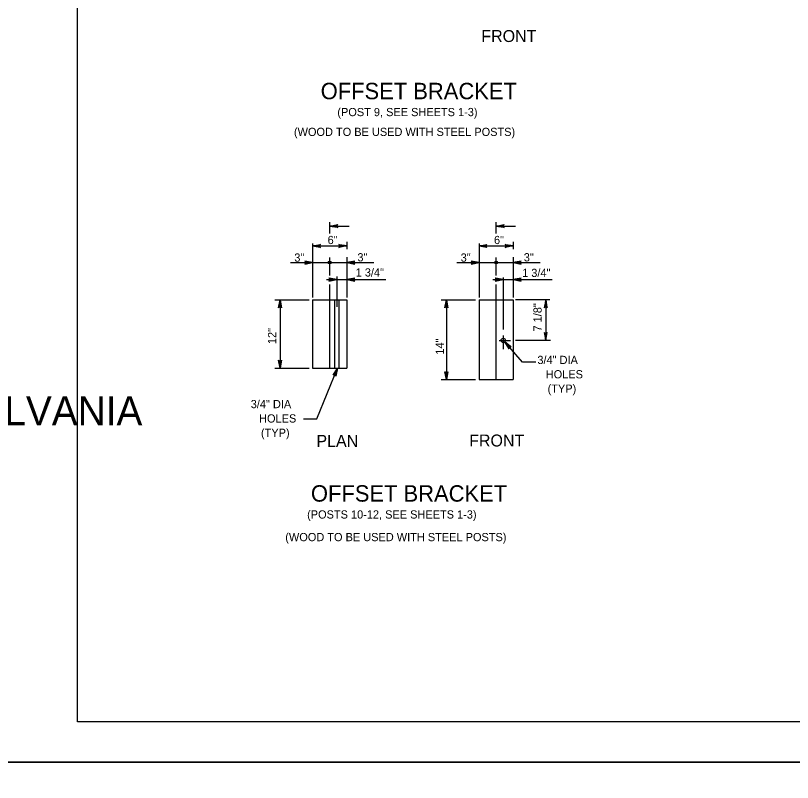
# Model space of a CAD drawing. Extents: x 632007860 to 635435983, y 295418622 to 297794622.
# Drawn here: x 632865880 to 633154598, y 297193122 to 297477992 of the extents above; entities that cross this region are included whole.
import ezdxf

# ---------------------------------------------------------------- set-up
doc = ezdxf.new("R2010")
doc.units = 0
for name, color, linetype in [('1', 7, 'Continuous'), ('8', 7, 'Continuous'), ('PLT-BNDY', 7, 'Continuous'), ('S-DETL-DIMS', 7, 'Continuous'), ('S-DETL-T120', 7, 'Continuous'), ('S-DETL-T175', 7, 'Continuous'), ('S-DETL-T240', 7, 'Continuous'), ('S-MISC-CNTR-WT01', 7, 'Continuous'), ('S-STEL', 7, 'Continuous')]:
    doc.layers.add(name, color=color, linetype=linetype)

msp = doc.modelspace()

# ---------------------------------------------------------------- linework, layer by layer
at = {"layer": '1'}
for p, q in [((632888860, 297215622), (632888860, 297779622)), ((633674860, 297215622), (632888860, 297215622))]:
    msp.add_line(p, q, dxfattribs=at)
at = {"layer": '8'}
for p, q in [((633044469, 297397026), (633044469, 297401243)), ((632982643, 297381483), (632982643, 297388087)), ((633044469, 297381483), (633044469, 297388087)), ((632985298, 297381047), (632985298, 297369752)), ((632982643, 297346747), (632982643, 297378051)), ((633044469, 297343001), (633044469, 297378051)), ((633045557, 297357298), (633049822, 297357298)), ((633047123, 297359084), (633047123, 297354089))]:
    msp.add_line(p, q, dxfattribs=at)
at = {"layer": 'PLT-BNDY'}
for points in [[(632848860, 297794622), (633689860, 297794622), (633689860, 297200622), (632848860, 297200622)], [(632848860, 297200622), (633689860, 297200622), (633689860, 296606622), (632848860, 296606622)]]:
    msp.add_lwpolyline(points, close=True, dxfattribs=at)
at = {"layer": 'S-DETL-DIMS'}
for p, q in [((632982643, 297399763), (632989870, 297399763)), ((633044469, 297399763), (633051696, 297399763)), ((632976285, 297393351), (632976285, 297373261)), ((632976285, 297392393), (632989001, 297392393)), ((632989001, 297393994), (632989001, 297391165)), ((633038111, 297393351), (633038111, 297373261)), ((633038111, 297392393), (633050827, 297392393)), ((633050827, 297393994), (633050827, 297391165)), ((632968104, 297386253), (632982643, 297386253)), ((632982643, 297386253), (632999058, 297386253)), ((632989001, 297388272), (632989001, 297373261)), ((633029930, 297386253), (633044469, 297386253)), ((633044469, 297386253), (633060884, 297386253)), ((633050827, 297388272), (633050827, 297373261)), ((632981467, 297379903), (633003476, 297379903)), ((633043293, 297379903), (633065302, 297379903)), ((633047123, 297380749), (633047123, 297361351)), ((632962247, 297372380), (632974964, 297372380)), ((632964195, 297372380), (632964195, 297346980)), ((633024073, 297372380), (633036790, 297372380)), ((633026021, 297372380), (633026021, 297342747)), ((633064393, 297372380), (633051614, 297372380)), ((633062917, 297372380), (633062917, 297357298)), ((633054311, 297349238), (633047746, 297356807)), ((633064730, 297357298), (633051614, 297357298)), ((633059258, 297349238), (633054311, 297349238)), ((632962247, 297346980), (632974964, 297346980)), ((632977820, 297328187), (632985563, 297346980)), ((633024073, 297342747), (633036790, 297342747)), ((632972874, 297328187), (632977820, 297328187))]:
    msp.add_line(p, q, dxfattribs=at)
for points in [[(632982643, 297399763), (632985603, 297400318), (632985375, 297400160), (632985257, 297399962), (632985223, 297399763), (632985257, 297399565), (632985375, 297399366), (632985603, 297399208), (632982643, 297399763), (632985375, 297399366), (632985257, 297399565), (632982643, 297399763), (632985223, 297399763), (632985257, 297399962), (632982643, 297399763), (632985375, 297400160)], [(633044469, 297399763), (633047428, 297400318), (633047200, 297400160), (633047083, 297399962), (633047049, 297399763), (633047083, 297399565), (633047200, 297399366), (633047428, 297399208), (633044469, 297399763), (633047200, 297399366), (633047083, 297399565), (633044469, 297399763), (633047049, 297399763), (633047083, 297399962), (633044469, 297399763), (633047200, 297400160)], [(632976285, 297392393), (632979245, 297392948), (632979017, 297392790), (632978899, 297392591), (632978865, 297392393), (632978899, 297392194), (632979017, 297391996), (632979245, 297391838), (632976285, 297392393), (632979017, 297391996), (632978899, 297392194), (632976285, 297392393), (632978865, 297392393), (632978899, 297392591), (632976285, 297392393), (632979017, 297392790)], [(632989001, 297392393), (632986042, 297391838), (632986270, 297391996), (632986387, 297392194), (632986422, 297392393), (632986387, 297392591), (632986270, 297392790), (632986042, 297392948), (632989001, 297392393), (632986270, 297392790), (632986387, 297392591), (632989001, 297392393), (632986422, 297392393), (632986387, 297392194), (632989001, 297392393), (632986270, 297391996)], [(633038111, 297392393), (633041070, 297392948), (633040842, 297392790), (633040725, 297392591), (633040691, 297392393), (633040725, 297392194), (633040842, 297391996), (633041070, 297391838), (633038111, 297392393), (633040842, 297391996), (633040725, 297392194), (633038111, 297392393), (633040691, 297392393), (633040725, 297392591), (633038111, 297392393), (633040842, 297392790)], [(633050827, 297392393), (633047868, 297391838), (633048096, 297391996), (633048213, 297392194), (633048247, 297392393), (633048213, 297392591), (633048096, 297392790), (633047868, 297392948), (633050827, 297392393), (633048096, 297392790), (633048213, 297392591), (633050827, 297392393), (633048247, 297392393), (633048213, 297392194), (633050827, 297392393), (633048096, 297391996)], [(632976285, 297386253), (632973326, 297386808), (632973554, 297386650), (632973672, 297386452), (632973706, 297386253), (632973672, 297386055), (632973554, 297385857), (632973326, 297385699), (632976285, 297386253), (632973554, 297385857), (632973672, 297386055), (632976285, 297386253), (632973706, 297386253), (632973672, 297386452), (632976285, 297386253), (632973554, 297386650)], [(632989001, 297386253), (632991961, 297385699), (632991732, 297385857), (632991615, 297386055), (632991581, 297386253), (632991615, 297386452), (632991732, 297386650), (632991961, 297386808), (632989001, 297386253), (632991732, 297386650), (632991615, 297386452), (632989001, 297386253), (632991581, 297386253), (632991615, 297386055), (632989001, 297386253), (632991732, 297385857)], [(633038111, 297386253), (633035152, 297386808), (633035380, 297386650), (633035497, 297386452), (633035531, 297386253), (633035497, 297386055), (633035380, 297385857), (633035152, 297385699), (633038111, 297386253), (633035380, 297385857), (633035497, 297386055), (633038111, 297386253), (633035531, 297386253), (633035497, 297386452), (633038111, 297386253), (633035380, 297386650)], [(633050827, 297386253), (633053786, 297385699), (633053558, 297385857), (633053441, 297386055), (633053407, 297386253), (633053441, 297386452), (633053558, 297386650), (633053786, 297386808), (633050827, 297386253), (633053558, 297386650), (633053441, 297386452), (633050827, 297386253), (633053407, 297386253), (633053441, 297386055), (633050827, 297386253), (633053558, 297385857)], [(632985298, 297379903), (632982339, 297380458), (632982453, 297380379), (632982567, 297380300), (632982625, 297380201), (632982684, 297380102), (632982701, 297380003), (632982718, 297379903), (632982701, 297379804), (632982684, 297379705), (632982625, 297379606), (632982567, 297379507), (632982453, 297379428), (632982339, 297379349), (632985298, 297379903), (632982453, 297379428), (632982567, 297379507), (632985298, 297379903), (632982625, 297379606), (632982684, 297379705), (632985298, 297379903), (632982701, 297379804), (632982718, 297379903), (632985298, 297379903), (632982701, 297380003), (632982684, 297380102), (632985298, 297379903), (632982625, 297380201), (632982567, 297380300), (632985298, 297379903), (632982453, 297380379)], [(632989001, 297379903), (632991961, 297379349), (632991847, 297379428), (632991732, 297379507), (632991674, 297379606), (632991615, 297379705), (632991598, 297379804), (632991581, 297379903), (632991598, 297380003), (632991615, 297380102), (632991674, 297380201), (632991732, 297380300), (632991847, 297380379), (632991961, 297380458), (632989001, 297379903), (632991847, 297380379), (632991732, 297380300), (632989001, 297379903), (632991674, 297380201), (632991615, 297380102), (632989001, 297379903), (632991598, 297380003), (632991581, 297379903), (632989001, 297379903), (632991598, 297379804), (632991615, 297379705), (632989001, 297379903), (632991674, 297379606), (632991732, 297379507), (632989001, 297379903), (632991847, 297379428)], [(633047123, 297379903), (633044163, 297380458), (633044277, 297380379), (633044391, 297380300), (633044450, 297380201), (633044509, 297380102), (633044526, 297380003), (633044543, 297379903), (633044526, 297379804), (633044509, 297379705), (633044450, 297379606), (633044391, 297379507), (633044277, 297379428), (633044163, 297379349), (633047123, 297379903), (633044277, 297379428), (633044391, 297379507), (633047123, 297379903), (633044450, 297379606), (633044509, 297379705), (633047123, 297379903), (633044526, 297379804), (633044543, 297379903), (633047123, 297379903), (633044526, 297380003), (633044509, 297380102), (633047123, 297379903), (633044450, 297380201), (633044391, 297380300), (633047123, 297379903), (633044277, 297380379)], [(633050827, 297379903), (633053786, 297379349), (633053672, 297379428), (633053558, 297379507), (633053499, 297379606), (633053441, 297379705), (633053424, 297379804), (633053407, 297379903), (633053424, 297380003), (633053441, 297380102), (633053499, 297380201), (633053558, 297380300), (633053672, 297380379), (633053786, 297380458), (633050827, 297379903), (633053672, 297380379), (633053558, 297380300), (633050827, 297379903), (633053499, 297380201), (633053441, 297380102), (633050827, 297379903), (633053424, 297380003), (633053407, 297379903), (633050827, 297379903), (633053424, 297379804), (633053441, 297379705), (633050827, 297379903), (633053499, 297379606), (633053558, 297379507), (633050827, 297379903), (633053672, 297379428)], [(632964195, 297372380), (632964750, 297369421), (632964592, 297369649), (632964393, 297369766), (632964195, 297369801), (632963997, 297369766), (632963798, 297369649), (632963640, 297369421), (632964195, 297372380), (632963798, 297369649), (632963997, 297369766), (632964195, 297372380), (632964195, 297369801), (632964393, 297369766), (632964195, 297372380), (632964592, 297369649)], [(633026021, 297372380), (633026576, 297369421), (633026418, 297369649), (633026219, 297369766), (633026021, 297369801), (633025822, 297369766), (633025624, 297369649), (633025466, 297369421), (633026021, 297372380), (633025624, 297369649), (633025822, 297369766), (633026021, 297372380), (633026021, 297369801), (633026219, 297369766), (633026021, 297372380), (633026418, 297369649)], [(633062917, 297372380), (633062362, 297369421), (633062520, 297369649), (633062719, 297369766), (633062917, 297369801), (633063116, 297369766), (633063314, 297369649), (633063472, 297369421), (633062917, 297372380), (633063314, 297369649), (633063116, 297369766), (633062917, 297372380), (633062917, 297369801), (633062719, 297369766), (633062917, 297372380), (633062520, 297369649)], [(633062917, 297357298), (633063472, 297360257), (633063314, 297360029), (633063116, 297359911), (633062917, 297359877), (633062719, 297359911), (633062520, 297360029), (633062362, 297360257), (633062917, 297357298), (633062520, 297360029), (633062719, 297359911), (633062917, 297357298), (633062917, 297359877), (633063116, 297359911), (633062917, 297357298), (633063314, 297360029)], [(633047746, 297356807), (633050104, 297354935), (633049970, 297354969), (633049836, 297355004), (633049722, 297354983), (633049609, 297354962), (633049523, 297354910), (633049437, 297354858), (633049373, 297354780), (633049309, 297354702), (633049273, 297354593), (633049236, 297354483), (633049251, 297354346), (633049266, 297354208), (633047746, 297356807), (633049251, 297354346), (633049236, 297354483), (633047746, 297356807), (633049273, 297354593), (633049309, 297354702), (633047746, 297356807), (633049373, 297354780), (633049437, 297354858), (633047746, 297356807), (633049523, 297354910), (633049609, 297354962), (633047746, 297356807), (633049722, 297354983), (633049836, 297355004), (633047746, 297356807), (633049970, 297354969)], [(632964195, 297346980), (632963640, 297349939), (632963798, 297349711), (632963997, 297349594), (632964195, 297349560), (632964393, 297349594), (632964592, 297349711), (632964750, 297349939), (632964195, 297346980), (632964592, 297349711), (632964393, 297349594), (632964195, 297346980), (632964195, 297349560), (632963997, 297349594), (632964195, 297346980), (632963798, 297349711)], [(632985563, 297346980), (632984949, 297344033), (632984919, 297344168), (632984890, 297344304), (632984820, 297344396), (632984751, 297344488), (632984666, 297344541), (632984581, 297344595), (632984482, 297344617), (632984384, 297344639), (632984270, 297344623), (632984156, 297344606), (632984039, 297344531), (632983923, 297344455), (632985563, 297346980), (632984039, 297344531), (632984156, 297344606), (632985563, 297346980), (632984270, 297344623), (632984384, 297344639), (632985563, 297346980), (632984482, 297344617), (632984581, 297344595), (632985563, 297346980), (632984666, 297344541), (632984751, 297344488), (632985563, 297346980), (632984820, 297344396), (632984890, 297344304), (632985563, 297346980), (632984919, 297344168)], [(633026021, 297342747), (633025466, 297345706), (633025545, 297345592), (633025624, 297345478), (633025723, 297345419), (633025822, 297345360), (633025922, 297345343), (633026021, 297345326), (633026120, 297345343), (633026219, 297345360), (633026318, 297345419), (633026418, 297345478), (633026497, 297345592), (633026576, 297345706), (633026021, 297342747), (633026497, 297345592), (633026418, 297345478), (633026021, 297342747), (633026318, 297345419), (633026219, 297345360), (633026021, 297342747), (633026120, 297345343), (633026021, 297345326), (633026021, 297342747), (633025922, 297345343), (633025822, 297345360), (633026021, 297342747), (633025723, 297345419), (633025624, 297345478), (633026021, 297342747), (633025545, 297345592)]]:
    msp.add_lwpolyline(points, dxfattribs=at)
for centre, radius in [((632982643, 297386253), 529), ((632982643, 297386253), 265), ((633044469, 297386253), 529), ((633044469, 297386253), 265)]:
    msp.add_circle(centre, radius, dxfattribs=at)
at = {"layer": 'S-MISC-CNTR-WT01'}
msp.add_line((632982643, 297397026), (632982643, 297401243), dxfattribs=at)
at = {"layer": 'S-STEL'}
for p, q in [((632976285, 297372380), (632989001, 297372380)), ((632976285, 297372380), (632976285, 297346980)), ((632984504, 297346980), (632984504, 297372380)), ((632986092, 297346980), (632986092, 297372380)), ((632989001, 297372380), (632989001, 297346980)), ((633038111, 297372380), (633050827, 297372380)), ((633038111, 297372380), (633038111, 297342747)), ((633050827, 297372380), (633050827, 297342747)), ((632976285, 297346980), (632989001, 297346980)), ((633038111, 297342747), (633050827, 297342747))]:
    msp.add_line(p, q, dxfattribs=at)
msp.add_circle((633047123, 297357298), 794, dxfattribs=at)

# ---------------------------------------------------------------- texts
at = {"layer": '1'}
msp.add_text('COMMONWEALTH OF PENNSYLVANIA', height=10783.37, dxfattribs=at).set_placement((632647011, 297325766))
at = {"layer": 'S-DETL-T120'}
for s, height, p in [('(POST 9, SEE SHEETS 1-3)', 3048.07, (632985469, 297440620)), ('(WOOD TO BE USED WITH STEEL POSTS)', 3048.07, (632969339, 297433260)), ('6"', 3048.1, (632981847, 297393099)), ('6"', 3048.1, (633043673, 297393099)), ('3"', 3048.1, (632969470, 297386568)), ('3"', 3048.1, (632992913, 297386673)), ('3"', 3048.1, (633031295, 297386568)), ('3"', 3048.1, (633054739, 297386673)), ('1 3/4"', 3048.1, (632992284, 297381053)), ('1 3/4"', 3048.1, (633054132, 297380885)), ('3/4" DIA', 3048.1, (633059805, 297348549)), ('HOLES', 3048.1, (633062913, 297343214)), ('(TYP)', 3048.1, (633063609, 297337880)), ('3/4" DIA', 3048.1, (632953284, 297332150)), ('HOLES', 3048.1, (632956392, 297326816)), ('(TYP)', 3048.1, (632957088, 297321482)), ('(POSTS 10-12, SEE SHEETS 1-3)', 3048.07, (632974233, 297291150)), ('(WOOD TO BE USED WITH STEEL POSTS)', 3048.07, (632966117, 297282747))]:
    msp.add_text(s, height=height, dxfattribs=at).set_placement(p)
for s, p in [('7 1/8"', (633061391, 297360633)), ('12"', (632962739, 297355951)), ('14"', (633025071, 297352043))]:
    msp.add_text(s, height=3048.1, rotation=90, dxfattribs=at).set_placement(p)
at = {"layer": 'S-DETL-T175'}
for s, p in [('FRONT', (633038983, 297468159)), ('PLAN', (632977697, 297317784)), ('FRONT', (633034464, 297317921))]:
    msp.add_text(s, height=4442.5, dxfattribs=at).set_placement(p)
at = {"layer": 'S-DETL-T240'}
for p in [(632979272, 297446903), (632975656, 297297432)]:
    msp.add_text('OFFSET BRACKET', height=6096, dxfattribs=at).set_placement(p)

doc.saveas('drawing.dxf')
